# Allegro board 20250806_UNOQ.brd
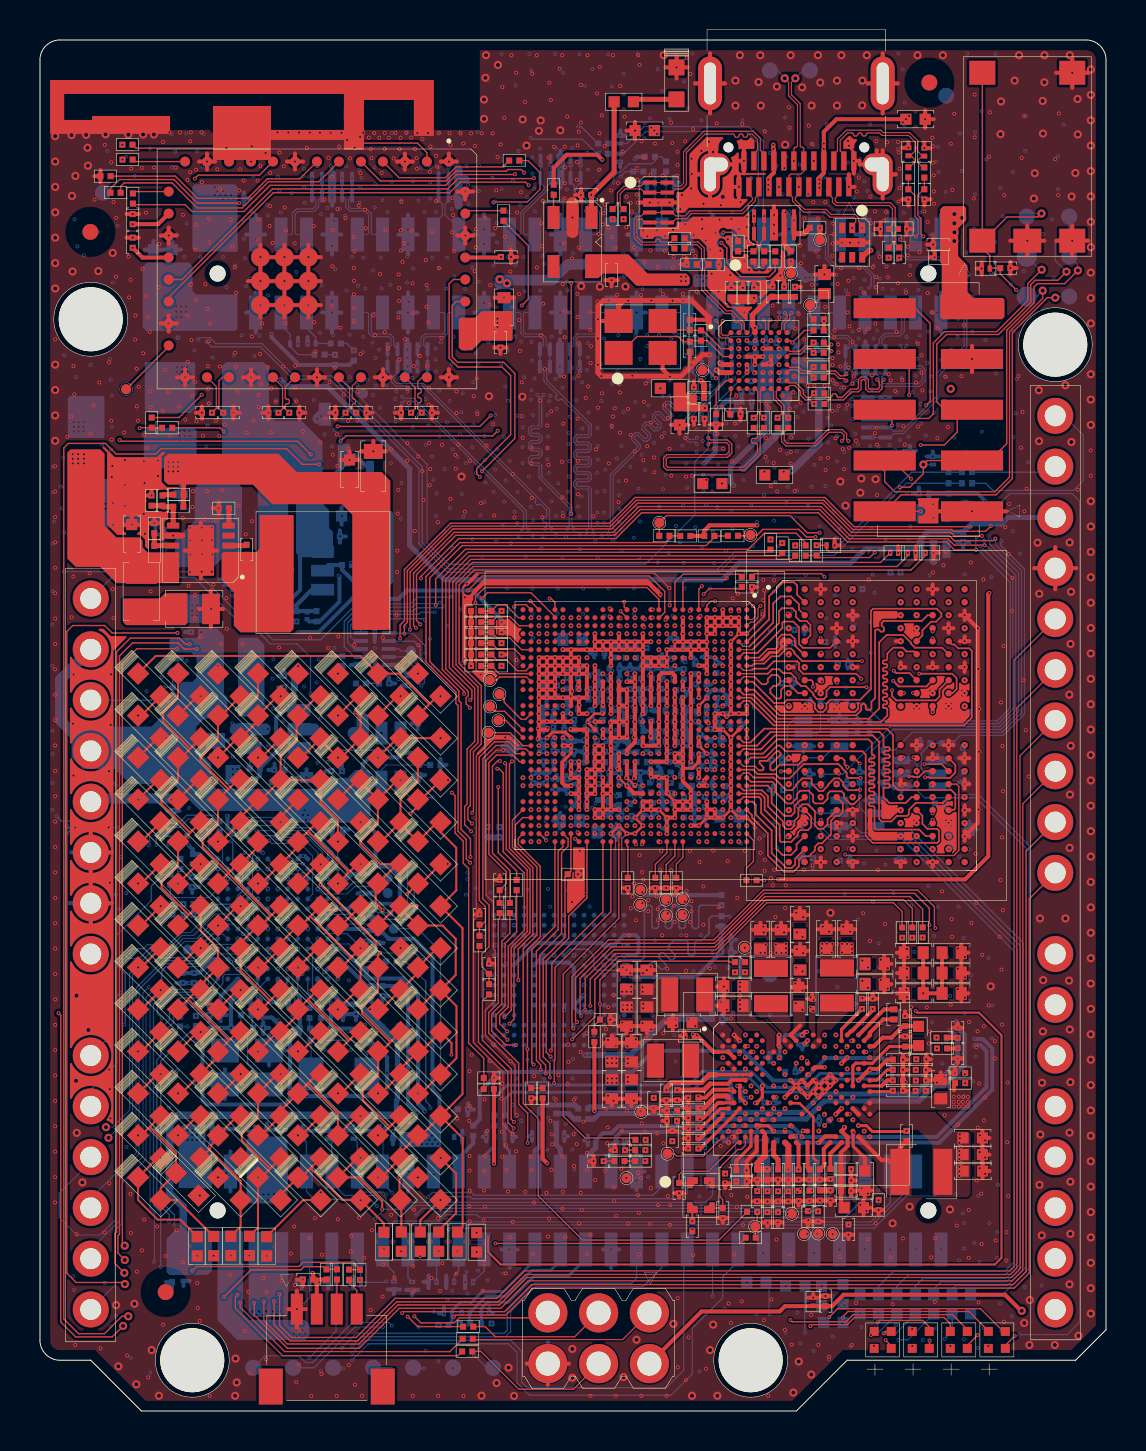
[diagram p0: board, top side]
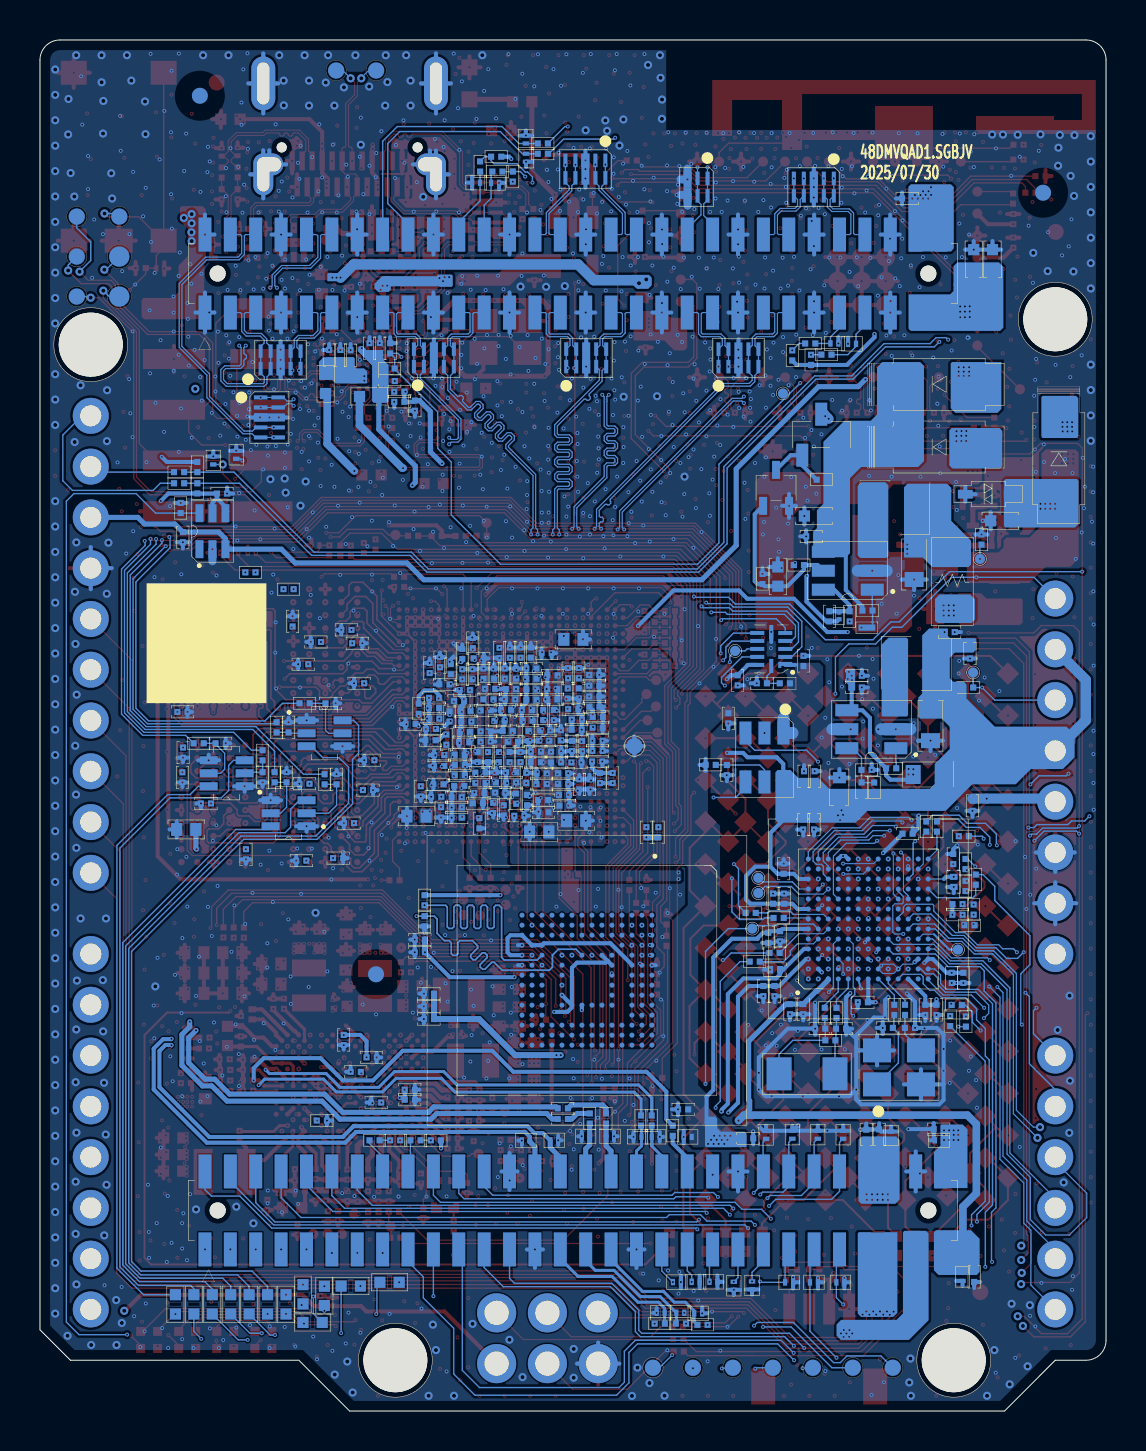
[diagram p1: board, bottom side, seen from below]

Outline 53.34 x 68.58 mm; copper layers: TOP, G2, S3, V4, V5, S6, G7, BOTTOM. Coordinates in mm from the lower left corner of the outline.
Outline path: 0,67.58 0,3.54 arc(0.29,2.83) 1,2.54 2.54,2.54 5.08,0 37.85,0 40.39,2.54 51.82,2.54 53.34,4.06 53.34,67.58 arc(53.05,68.29) 52.34,68.58 1,68.58 arc(0.29,68.29) 0,67.58

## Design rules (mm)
constraint set DEFAULT: min track width 0.066
net group DP_MUX_SSRXN1_C: nets MUX_SSRXN1_C MUX_SSRXP1_C
net group DP_MUX_SSRXN2_C: nets MUX_SSRXN2_C MUX_SSRXP2_C
net group EAR_M_R: nets EAR_M_R EAR_P_R
net group EBI0_CKE: nets EBI0_CKE_0 EBI0_CKE_1
net group EBI0_CLK: nets EBI0_CLK_M EBI0_CLK_P
net group EBI0_DQS_0: nets EBI0_DQS_0_M EBI0_DQS_0_P
net group EBI0_DQS_1: nets EBI0_DQS_1_M EBI0_DQS_1_P
net group EBI1_CKE: nets EBI1_CKE_0 EBI1_CKE_1
net group EBI1_CLK: nets EBI1_CLK_M EBI1_CLK_P
net group EBI1_DQS_0: nets EBI1_DQS_0_M EBI1_DQS_0_P
net group EBI1_DQS_1: nets EBI1_DQS_1_M EBI1_DQS_1_P
net group LINEOUT: nets LINEOUT_M LINEOUT_P
net group LINEOUT_CONN: nets LINEOUT_M_CONN LINEOUT_P_CONN
net group LINEOUT_P_C: nets LINEOUT_M_C LINEOUT_P_C
net group MG_CMD: nets WL_CMD_CLK WL_CMD_DATA
net group MIPI_DSI0_CLK_M: nets MIPI_DSI0_CLK_M MIPI_DSI0_CLK_M_CONN
net group MIPI_DSI0_CLK_P: nets MIPI_DSI0_CLK_P MIPI_DSI0_CLK_P_CONN
net group MIPI_DSI0_L0_M: nets MIPI_DSI0_L0_M MIPI_DSI0_L0_M_CONN
net group MIPI_DSI0_L0_P: nets MIPI_DSI0_L0_P MIPI_DSI0_L0_P_CONN
net group MIPI_DSI0_L1_M: nets MIPI_DSI0_L1_M MIPI_DSI0_L1_M_CONN
net group MIPI_DSI0_L1_P: nets MIPI_DSI0_L1_P MIPI_DSI0_L1_P_CONN
net group MIPI_DSI0_L3_M: nets MIPI_DSI0_L3_M MIPI_DSI0_L3_M_CONN
net group MIPI_DSI0_L3_P: nets MIPI_DSI0_L3_P MIPI_DSI0_L3_P_CONN
net group MUX_SBU1: nets MUX_SBU1 SBU1_AUXP
net group MUX_SBU2: nets MUX_SBU2 SBU2_AUXN
net group MUX_SSRXN2: nets MUX_SSRXN2 MUX_SSRXP2
net group MUX_SSRXP1: nets MUX_SSRXN1 MUX_SSRXP1
net group MUX_SSTXN1_C: nets MUX_SSTXN1 MUX_SSTXP1
net group MUX_SSTXN2: nets MUX_SSTXN2 MUX_SSTXP2
net group MUX_SSTXN2_C: nets MUX_SSTXN2_C MUX_SSTXP2_C
net group MUX_SSTXP1_C: nets MUX_SSTXN1_C MUX_SSTXP1_C
net group SDC1_CLK: nets SDC1_CLK SDC1_CLK_TR
net group VFB_S3: nets VFB_NEG_S3 VFB_S3
net group VFB_S4: nets VFB_NEG_S4 VFB_S4
net group VSNS_S1A_APC: nets VSNS_S1A_APC_M VSNS_S1A_APC_P
net group VSNS_S2A_CX: nets VSNS_S2A_CX_M VSNS_S2A_CX_P
net group CLS_CRITICAL: nets SOC_I2S_D0_R SOC_I2S_SCK SOC_I2S_SCK_R SOC_I2S_WS SOC_I2S_WS_R SOC_UART_RX_SE4 SOC_UART_TX_SE4
net group CLS_LED_MATRIX: nets LED_MATRIX_0 LED_MATRIX_0_R LED_MATRIX_1 LED_MATRIX_1_R LED_MATRIX_2 LED_MATRIX_2_R LED_MATRIX_3 LED_MATRIX_3_R LED_MATRIX_4 LED_MATRIX_4_R LED_MATRIX_5 LED_MATRIX_5_R LED_MATRIX_6 LED_MATRIX_6_R LED_MATRIX_7 LED_MATRIX_7_R LED_MATRIX_8 LED_MATRIX_8_R LED_MATRIX_9 LED_MATRIX_9_R LED_MATRIX_10 LED_MATRIX_10_R LED_MATRIX_11
net group CLS_POWER: nets AVDD1P0V AVDD1P8V AVDD3P0V DVDD1P0V DVDD1P8V VBUS_DIV8 VCOIN VCONN_IN VREF_LPDDR3 VREF_MSM_1P25V VREF_TXDAC_1P25V VREG_L3A_0P6V VREG_L4A_2P96V VREG_L5A_1P232V VREG_L6A_0P9V VREG_L7A_0P664V VREG_L8A_1P0V VREG_L9A_1P0V VREG_L10A_1P3V VREG_L11A_1P0V VREG_L12A_0P9V VREG_L13A_1P8V VREG_L14A_1P8V VREG_L16A_1P8V VREG_L17A_3P0V VREG_L18A_1P8V VREG_L19A_1P8V VREG_L21A_2P96V VREG_L22A_3P3V VREG_S1A_0P8V VREG_XO VSW_S1 VSW_S2 VSW_S3 VSW_S4
net group CLS_SINGEL-50R: nets ANT_CH0 FM_ANT LNBBCLK1 LNBBCLK2 LNBBCLK2_R MUX_XTAL_IN MUX_XTAL_OUT RFCLK2 RTC_SLEEP_CLK RTC_SLEEP_CLK_R SLEEP_CLK SM_LNBBCLK1 SWR_RX_CLK SWR_RX_CLK_R SWR_RX_DATA0 SWR_RX_DATA0_R SWR_RX_DATA1 SWR_RX_DATA1_R SWR_TX_CLK SWR_TX_CLK_R SWR_TX_DATA0 SWR_TX_DATA0_R WCN_RFCLK2 WCN_RFCLK2_R WLAN_XO_CLK
net group EBI0_CA_CS: nets EBI0_CA_0 EBI0_CA_1 EBI0_CA_2 EBI0_CA_3 EBI0_CA_4 EBI0_CA_5 EBI0_CS_0 EBI0_CS_1
net group EBI0_DQ0-7: nets EBI0_DMI_0 EBI0_DQ0 EBI0_DQ1 EBI0_DQ2 EBI0_DQ3 EBI0_DQ4 EBI0_DQ5 EBI0_DQ6 EBI0_DQ7
net group EBI0_DQ8_15: nets EBI0_DMI_1 EBI0_DQ8 EBI0_DQ9 EBI0_DQ10 EBI0_DQ11 EBI0_DQ12 EBI0_DQ13 EBI0_DQ14 EBI0_DQ15
net group EBI1_CA_CS: nets EBI1_CA_0 EBI1_CA_1 EBI1_CA_2 EBI1_CA_3 EBI1_CA_4 EBI1_CA_5 EBI1_CS_0 EBI1_CS_1
net group EBI1_DQ0_7: nets EBI1_DMI_0 EBI1_DQ0 EBI1_DQ1 EBI1_DQ2 EBI1_DQ3 EBI1_DQ4 EBI1_DQ5 EBI1_DQ6 EBI1_DQ7
net group EBI1_DQ8_15: nets EBI1_DMI_1 EBI1_DQ8 EBI1_DQ9 EBI1_DQ10 EBI1_DQ11 EBI1_DQ12 EBI1_DQ13 EBI1_DQ14 EBI1_DQ15
net group MIPI_DSI0_L2_M: nets MIPI_DSI0_L2_M
net group MIPI_DSI0_L2_P: nets MIPI_DSI0_L2_P
net group SDC1: nets SDC1_CMD SDC1_DATA_0 SDC1_DATA_1 SDC1_DATA_2 SDC1_DATA_3 SDC1_DATA_4 SDC1_DATA_5 SDC1_DATA_6 SDC1_DATA_7 SDC1_RCLK

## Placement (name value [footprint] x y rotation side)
ANT1  CLIP2P  [ANT2_1920X400]  15.71 64.83 0 top
C501  2.2UF/6.3V  [C0201_H04_T30]  42.72 19.84 0 top
C502  1UF/6.3V  [C0201_H040]  43.29 19.51 180 top
C503  1UF/6.3V  [C0201_H040]  43.29 18.49 180 top
C504  1UF/6.3V  [C0201_H040]  41.13 20.37 180 top
C505  1UF/6.3V  [C0201_H040]  42.93 17.58 90 top
C506  1UF/6.3V  [C0201_H040]  41.66 20.37 180 top
C507  680PF/25V  [C0201_H030]  42.93 17.07 90 top
C508  470PF/50V  [C0201_H030]  42.93 16.54 90 top
C509  680PF/25V  [C0201_H030]  42.93 16.02 90 top
C510  33PF/50V  [C0201_H030]  44.08 17.06 90 top
C511  33PF/50V  [C0201_H030]  44.08 16.53 90 top
C512  100NF/6.3V  [C0201_H030]  44.1 17.59 90 top
C513  100NF/6.3V  [C0201_H030]  27.18 14.61 270 bottom
C514  100NF/6.3V  [C0201_H030]  27.18 15.14 270 bottom
C601  4.7UF/10V  [C0402_H060]  40.72 10.17 90 top
C602  1UF/10V  [C0201_H030]  40.34 11.53 90 top
C603  100NF/10V  [C0201_H030]  40.34 11.01 90 top
C604  10UF/10V  [C0402_H060]  46.68 12 90 top
C605  10UF/10V  [C0402_H060]  46.67 12.83 90 top
C606  10UF/10V  [C0402_H060]  46.67 13.66 90 top
C607  10UF/6.3V  [C0402_H07_T30]  45.07 16.1 180 top
C608  4.7UF/10V  [C0402_H060]  41.27 11.52 0 top
C609  27NF/16V  [C0201_H030]  43.36 13.76 0 top
C610  4.7UF/6.3V  [C0201_H060]  40.46 9.07 0 top
C701  7PF/25V  [C0201_H030]  31.98 11.15 0 top
C702  7PF/25V  [C0201_H030]  34.16 9.91 0 top
C703  1000PF/50V  [C0201_H030]  32.64 9.25 180 top
C704  1UF/6.3V  [C0201_H040]  34.28 11.63 0 top
C705  1UF/6.3V  [C0201_H040]  35.1 11.48 90 top
C706  4.7UF/6.3V  [C0201_H060]  35.1 12.04 90 top
C707  10PF/50V  [C0201_H030]  29.02 13.05 270 top
C708  10UF/6.3V  [C0402_H07_T30]  43.71 22.92 270 top
C709  10UF/6.3V  [C0402_H07_T30]  45.62 22.92 90 top
C710  10UF/6.3V  [C0402_H07_T30]  45.62 21.91 90 top
C711  10UF/6.3V  [C0402_H07_T30]  43.71 21.91 270 top
C712  10UF/6.3V  [C0402_H07_T30]  45.62 20.89 90 top
C713  10UF/6.3V  [C0402_H07_T30]  43.71 20.89 270 top
C714  1UF/6.3V  [C0201_H040]  31.62 15.02 270 top
C715  1UF/6.3V  [C0201_H040]  31.62 14.51 270 top
C716  100NF/10V  [C0201_H030]  31.64 13.75 180 top
C717  100NF/10V  [C0201_H030]  36.4 9.69 0 top
C718  100NF/6.3V  [C0201_H030]  38.5 10.77 0 top
C719  100NF/6.3V  [C0201_H030]  30.71 15.41 0 top
C720  0  [C0201_H030]  28.99 12.5 270 top
C721  22PF/50V  [C0201_H030]  27.95 12.5 270 top
C801  1UF/6.3V  [C0201_H040]  38.14 18.56 180 bottom
C802  1UF/6.3V  [C0201_H040]  36.75 17.69 90 bottom
C803  1UF/6.3V  [C0201_H040]  34.84 15.57 90 bottom
C804  1UF/6.3V  [C0201_H040]  34.84 16.07 90 bottom
C805  1UF/6.3V  [C0201_H040]  35.89 10.74 0 top
C806  10UF/6.3V  [C0402_H07_T30]  34.7 20.28 270 top
C807  10UF/6.3V  [C0402_H07_T30]  34.7 21.23 270 top
C808  10UF/6.3V  [C0402_H07_T30]  41.76 21.35 90 top
C809  10UF/6.3V  [C0402_H07_T30]  41.76 22.36 90 top
C810  10UF/6.3V  [C0402_H07_T30]  38.02 24.33 180 top
C811  10UF/6.3V  [C0402_H07_T30]  38.03 22.54 180 top
C812  1UF/6.3V  [C0201_H040]  37.96 11.83 0 top
C813  1UF/6.3V  [C0201_H040]  32.69 14.15 270 top
C814  1UF/6.3V  [C0201_H040]  32.69 13.64 270 top
C815  2.2UF/6.3V  [C0201_H030]  32.69 14.66 270 top
C816  2.2UF/6.3V  [C0201_H030]  31.88 15.8 0 top
C817  1UF/6.3V  [C0201_H040]  32.69 15.67 270 top
C818  4.7UF/6.3V  [C0201_H060]  31.34 15.8 0 top
C819  2.2UF/6.3V  [C0201_H030]  32.69 15.16 270 top
C820  2.2UF/6.3V  [C0201_H030]  32.69 13.13 270 top
C821  2.2UF/6.3V  [C0201_H030]  37.45 10.74 0 top
C822  4.7UF/6.3V  [C0201_H060]  37.45 11.83 0 top
C823  4.7UF/6.3V  [C0201_H060]  36.4 11.83 0 top
C824  1UF/6.3V  [C0201_H040]  35.89 11.83 0 top
C825  2.2UF/6.3V  [C0201_H030]  36.93 11.83 0 top
C826  4.7UF/6.3V  [C0201_H060]  38.51 11.83 0 top
C827  1UF/6.3V  [C0201_H040]  39.55 11.85 0 top
C828  1UF/6.3V  [C0201_H040]  39.02 11.83 0 top
C829  4.7UF/6.3V  [C0201_H060]  37.96 10.76 0 top
C830  4.7UF/6.3V  [C0201_H060]  36.93 10.74 0 top
C831  4.7UF/6.3V  [C0201_H060]  39.03 10.79 0 top
C832  1UF/6.3V  [C0201_H040]  39.55 10.79 0 top
C901  1UF/10V  [C0201_H030]  36.52 15.43 270 bottom
C902  1UF/10V  [C0201_H030]  37.54 16.97 270 bottom
C1001  1UF/10V  [C0201_H030]  38.63 20.37 180 top
C1002  10UF/10V  [C0402_H060]  37.97 20.73 180 top
C1003  10UF/10V  [C0402_H060]  32.15 19.43 270 top
C1004  1UF/10V  [C0201_H030]  32.5 18.76 270 top
C1005  10UF/6.3V  [C0402_H07_T30]  29.35 19.73 0 top
C1006  10UF/6.3V  [C0402_H07_T30]  29.35 21.57 180 top
C1007  10UF/6.3V  [C0402_H07_T30]  30.37 21.57 180 top
C1008  10UF/6.3V  [C0402_H07_T30]  30.37 19.73 0 top
C1009  10UF/6.3V  [C0402_H07_T30]  29.6 17.94 180 top
C1010  10UF/6.3V  [C0402_H07_T30]  28.61 16.1 0 top
C1011  10UF/6.3V  [C0402_H07_T30]  28.61 17.94 180 top
C1012  10UF/6.3V  [C0402_H07_T30]  29.6 16.1 0 top
C1101  100NF/6.3V  [C0201_H030]  15.14 37.52 0 bottom
C1102  100NF/6.3V  [C0201_H030]  18.43 36.55 180 bottom
C1103  100NF/6.3V  [C0201_H030]  18.9 34.65 180 bottom
C1104  100NF/6.3V  [C0201_H030]  14.58 31.75 0 bottom
C1105  4.7UF/6.3V  [C0201_H060]  17.22 36.4 270 bottom
C1106  4.7UF/6.3V  [C0201_H060]  18.97 32.06 180 bottom
C1201  100NF/6.3V  [C0201_H030]  23 26.31 180 top
C1202  33PF/50V  [C0201_H030]  21.99 24.59 180 top
C1203  33PF/50V  [C0201_H030]  22.47 22.12 180 top
C1601  2.7PF/50V  [C0201_H030]  19.35 49.94 90 top
C1602  2.7PF/50V  [C0201_H030]  18.31 49.94 270 top
C1603  2.7PF/50V  [C0201_H030]  9.42 49.94 90 top
C1604  2.7PF/50V  [C0201_H030]  8.36 49.94 270 top
C1701  1UF/6.3V  [C0201_H040]  30.38 32.71 180 bottom
C1702  100NF/6.3V  [C0201_H030]  24.68 31.66 180 bottom
C1703  100NF/6.3V  [C0201_H030]  25.32 31.66 180 bottom
C1704  100NF/6.3V  [C0201_H030]  26.66 35.11 90 bottom
C1705  10UF/6.3V  [C0402_H07_T30]  26.51 29.53 90 bottom
C1706  10UF/6.3V  [C0402_H07_T30]  39.34 23.62 180 top
C1707  10UF/6.3V  [C0402_H07_T30]  28.36 28.97 270 bottom
C1708  10UF/6.3V  [C0402_H07_T30]  40.37 23.62 180 top
C1709  100NF/6.3V  [C0201_H030]  27.51 32.44 90 bottom
C1710  100NF/6.3V  [C0201_H030]  28.53 32.45 270 bottom
C1711  2.2UF/6.3V  [C0201_H030]  29.77 31.95 270 bottom
C1712  2.2UF/6.3V  [C0201_H030]  29.85 32.71 0 bottom
C1713  100NF/6.3V  [C0201_H030]  28.24 31.9 270 bottom
C1714  470NF/6.3V  [C0201_H030]  27.12 30.82 90 bottom
C1715  470NF/6.3V  [C0201_H030]  28.24 31.36 270 bottom
C1716  470NF/6.3V  [C0201_H030]  29.29 32.71 0 bottom
C1717  100NF/6.3V  [C0201_H030]  27.51 32.98 90 bottom
C1718  100NF/6.3V  [C0201_H030]  28.97 30.56 180 bottom
C1719  100NF/6.3V  [C0201_H030]  28.53 32.98 270 bottom
C1720  100NF/6.3V  [C0201_H030]  27.16 31.36 90 bottom
C1721  100NF/6.3V  [C0201_H030]  27.09 30.28 90 bottom
C1722  2.2UF/6.3V  [C0201_H030]  28.11 33.53 270 bottom
C1723  2.2UF/6.3V  [C0201_H030]  28.15 29.95 270 bottom
C1724  100NF/6.3V  [C0201_H030]  27.16 31.9 90 bottom
C1725  100NF/6.3V  [C0201_H030]  28.16 30.56 270 bottom
C1727  4.7UF/6.3V  [C0201_H060]  32.33 31.8 90 bottom
C1728  2.2UF/6.3V  [C0201_H030]  28.78 37.94 0 bottom
C1729  100NF/6.3V  [C0201_H030]  31.04 35.04 90 bottom
C1730  100NF/6.3V  [C0201_H030]  31.04 34 90 bottom
C1731  100NF/6.3V  [C0201_H030]  32.34 32.82 90 bottom
C1732  470NF/6.3V  [C0201_H030]  28.75 36.09 270 bottom
C1733  10NF/10V  [C0201_H030]  32.37 35.52 90 bottom
C1734  1UF/6.3V  [C0201_H040]  28.75 35.58 270 bottom
C1735  1UF/6.3V  [C0201_H040]  28.94 34.54 270 bottom
C1736  2.2UF/6.3V  [C0201_H030]  31.04 33.49 90 bottom
C1737  2.2UF/6.3V  [C0201_H030]  31.14 36.89 0 bottom
C1738  470NF/6.3V  [C0201_H030]  32.85 34.74 180 bottom
C1739  100NF/6.3V  [C0201_H030]  30.81 36.12 90 bottom
C1740  100NF/6.3V  [C0201_H030]  28.75 37.14 270 bottom
C1741  100NF/6.3V  [C0201_H030]  28.75 36.63 270 bottom
C1742  1UF/6.3V  [C0201_H040]  31.44 32.72 180 bottom
C1743  1UF/6.3V  [C0201_H040]  26.5 32.44 90 bottom
C1801  10UF/6.3V  [C0402_H07_T30]  34.5 29.76 270 bottom
C1802  10UF/6.3V  [C0402_H07_T30]  26.65 38.6 90 bottom
C1803  10UF/6.3V  [C0402_H07_T30]  36.04 23.59 180 top
C1804  10UF/6.3V  [C0402_H07_T30]  37.08 23.59 180 top
C1805  1UF/6.3V  [C0201_H040]  27.7 36.8 270 bottom
C1806  1UF/6.3V  [C0201_H040]  27.7 36.12 270 bottom
C1807  2.2UF/6.3V  [C0201_H030]  27.63 34.81 180 bottom
C1808  100NF/6.3V  [C0201_H030]  29.81 35.6 270 bottom
C1809  100NF/6.3V  [C0201_H030]  29.94 34.01 270 bottom
C1810  100NF/6.3V  [C0201_H030]  32.08 36.06 270 bottom
C1811  100NF/6.3V  [C0201_H030]  32.08 33.96 270 bottom
C1812  100NF/6.3V  [C0201_H030]  30.9 35.6 270 bottom
C1813  100NF/6.3V  [C0201_H030]  27.71 35.6 270 bottom
C1814  1UF/6.3V  [C0201_H040]  30.02 35.08 270 bottom
C1815  1UF/6.3V  [C0201_H040]  32.12 33.46 270 bottom
C1816  1UF/6.3V  [C0201_H040]  30.34 34.53 90 bottom
C1817  1UF/6.3V  [C0201_H040]  31.3 31.93 90 bottom
C1818  4.7UF/6.3V  [C0201_H060]  30.61 36.89 0 bottom
C1819  470NF/6.3V  [C0201_H030]  29.78 36.11 270 bottom
C1820  2.2UF/6.3V  [C0201_H030]  29.52 36.88 0 bottom
C1821  100NF/6.3V  [C0201_H030]  32.05 35.01 270 bottom
C1822  1UF/6.3V  [C0201_H040]  30.08 36.89 0 bottom
C1823  1UF/6.3V  [C0201_H040]  29.68 33.48 90 bottom
C1824  4.7UF/6.3V  [C0201_H060]  28.06 34.04 90 bottom
C1825  100NF/6.3V  [C0201_H030]  28.89 33.77 180 bottom
C1826  2.2UF/6.3V  [C0201_H030]  26.21 33.27 180 bottom
C1827  100NF/6.3V  [C0201_H030]  26.72 33.27 180 bottom
C1828  100NF/6.3V  [C0201_H030]  27.27 33.8 0 bottom
C1829  1UF/6.3V  [C0201_H040]  25.44 33.53 270 bottom
C1830  1UF/6.3V  [C0201_H040]  34.29 31 180 bottom
C1831  1UF/6.3V  [C0201_H040]  33.84 37.17 0 bottom
C1833  1UF/6.3V  [C0201_H040]  27.99 37.91 270 bottom
C1834  1UF/6.3V  [C0201_H040]  26.35 31.34 0 bottom
C1835  1UF/6.3V  [C0201_H040]  30.92 32.71 180 bottom
C1836  100NF/6.3V  [C0201_H030]  33.51 30.73 270 bottom
C1837  1UF/6.3V  [C0201_H040]  30.35 37.92 180 bottom
C1838  1UF/6.3V  [C0201_H040]  29.35 29.77 90 bottom
C1839  1UF/6.3V  [C0201_H040]  33.36 32.27 270 bottom
C1840  1UF/6.3V  [C0201_H040]  25.44 33.02 270 bottom
C1841  1UF/6.3V  [C0201_H040]  25.84 31.34 0 bottom
C1842  1UF/6.3V  [C0201_H040]  33.27 29.95 180 bottom
C1843  100NF/6.3V  [C0201_H030]  25.46 32.49 90 bottom
C1844  100NF/6.3V  [C0201_H030]  29.51 30.63 0 bottom
C1845  4.7UF/6.3V  [C0201_H060]  32.21 37.87 0 bottom
C1846  4.7UF/6.3V  [C0201_H060]  31.7 36.85 0 bottom
C1847  470NF/6.3V  [C0201_H030]  32.21 36.85 0 bottom
C1848  470NF/6.3V  [C0201_H030]  32.78 37.11 0 bottom
C1849  4.7UF/6.3V  [C0201_H060]  28.98 35.06 270 bottom
C1850  470NF/6.3V  [C0201_H030]  33.36 32.81 270 bottom
C1851  1UF/6.3V  [C0201_H040]  25.44 34.18 90 bottom
C1901  1UF/6.3V  [C0201_H040]  29.01 31.66 0 bottom
C1902  1UF/6.3V  [C0201_H040]  33.1 36.35 270 bottom
C1903  1UF/6.3V  [C0201_H040]  32.33 32.31 90 bottom
C1904  1UF/6.3V  [C0201_H040]  30.14 30.05 180 bottom
C1905  1UF/6.3V  [C0201_H040]  29.83 37.93 0 bottom
C1906  100NF/6.3V  [C0201_H030]  29.29 37.93 0 bottom
C1907  100NF/6.3V  [C0201_H030]  30.31 30.93 90 bottom
C1908  1UF/6.3V  [C0201_H040]  30.53 31.7 0 bottom
C1909  1UF/6.3V  [C0201_H040]  30.66 30.17 180 bottom
C1910  1UF/6.3V  [C0201_H040]  29.77 31.44 270 bottom
C1911  100NF/6.3V  [C0201_H030]  26.48 34.59 90 bottom
C1912  470NF/6.3V  [C0201_H030]  28.16 34.82 180 bottom
C1913  1UF/6.3V  [C0201_H040]  31.39 37.65 90 bottom
C1914  1UF/6.3V  [C0201_H040]  32.01 34.48 270 bottom
C1915  1UF/6.3V  [C0201_H040]  33.61 34.63 270 bottom
C1916  1UF/6.3V  [C0201_H040]  33.62 35.16 270 bottom
C1917  1UF/6.3V  [C0201_H040]  26.49 34.08 90 bottom
C1918  100NF/6.3V  [C0201_H030]  25.43 34.72 90 bottom
C1919  100NF/6.3V  [C0201_H030]  25.61 35.74 90 bottom
C1920  100NF/6.3V  [C0201_H030]  25.61 36.28 90 bottom
C1921  1UF/6.3V  [C0201_H040]  25.61 36.82 90 bottom
C1922  100NF/6.3V  [C0201_H030]  26.92 36.91 0 bottom
C1923  100NF/6.3V  [C0201_H030]  26.38 36.91 0 bottom
C1924  1UF/6.3V  [C0201_H040]  26.93 35.89 180 bottom
C1925  470NF/6.3V  [C0201_H030]  33.4 31.35 270 bottom
C1926  100NF/6.3V  [C0201_H030]  32.49 30.7 270 bottom
C1927  100NF/6.3V  [C0201_H030]  32.36 31.27 270 bottom
C1928  100NF/6.3V  [C0201_H030]  32.49 30.19 270 bottom
C1929  1UF/6.3V  [C0201_H040]  32.49 29.68 270 bottom
C1930  1UF/6.3V  [C0201_H040]  31.43 30.4 90 bottom
C1931  1UF/6.3V  [C0201_H040]  31.35 29.4 180 bottom
C1932  1UF/6.3V  [C0201_H040]  31.35 30.92 90 bottom
C1933  1UF/6.3V  [C0201_H040]  31.3 31.42 90 bottom
C1934  1UF/6.3V  [C0201_H040]  33.78 34.11 270 bottom
C1935  1UF/6.3V  [C0201_H040]  31.68 38.41 0 bottom
C1936  2.2UF/6.3V  [C0201_H030]  33.62 35.67 270 bottom
C1937  1UF/6.3V  [C0201_H040]  33.32 37.46 0 bottom
C1938  2.2UF/6.3V  [C0201_H030]  33.01 33.58 180 bottom
C1939  100NF/6.3V  [C0201_H030]  25.6 35.23 90 bottom
C1940  100NF/6.3V  [C0201_H030]  26.38 35.89 180 bottom
C2101  1UF/6.3V  [C0201_H040]  22.4 28.95 0 bottom
C2102  100NF/10V  [C0201_H030]  23 28.95 0 bottom
C2103  2.2UF/6.3V  [C0201_H030]  33.88 20.24 270 bottom
C2104  100NF/6.3V  [C0201_H030]  33.88 20.88 270 bottom
C2105  2.2UF/6.3V  [C0201_H030]  33.88 19.61 270 bottom
C2106  2.2UF/6.3V  [C0201_H030]  34.33 23.58 270 bottom
C2107  1UF/6.3V  [C0201_H040]  34.33 22.95 270 bottom
C2201  1UF/6.3V  [C0201_H040]  38.01 39.07 270 bottom
C2202  1UF/6.3V  [C0201_H040]  40.7 39.5 0 bottom
C2203  1UF/6.3V  [C0201_H040]  33.8 33.55 270 bottom
C2204  100NF/6.3V  [C0201_H030]  38.42 27.66 90 bottom
C2205  1UF/6.3V  [C0201_H040]  43.03 27.85 180 bottom
C2206  1UF/6.3V  [C0201_H040]  37.88 29.41 270 bottom
C2207  100NF/6.3V  [C0201_H030]  45.03 30.39 270 bottom
C2208  1UF/6.3V  [C0201_H040]  39.53 38.47 270 bottom
C2209  1UF/6.3V  [C0201_H040]  37.37 36.4 270 bottom
C2210  1UF/6.3V  [C0201_H040]  34.8 34.36 270 bottom
C2211  1UF/6.3V  [C0201_H040]  46.21 34.97 90 bottom
C2212  1UF/6.3V  [C0201_H040]  46.21 31.7 180 bottom
C2213  1UF/6.3V  [C0201_H040]  40.27 27.53 270 bottom
C2214  1UF/6.3V  [C0201_H040]  46.18 32.94 180 bottom
C2215  10UF/6.3V  [C0402_H07_T30]  46.02 29.09 270 bottom
C2216  4.7UF/6.3V  [C0201_H060]  36.86 32.55 270 bottom
C2217  100NF/6.3V  [C0201_H030]  40.11 31.38 270 bottom
C2218  1UF/6.3V  [C0201_H040]  37.47 38.41 90 bottom
C2219  1UF/6.3V  [C0201_H040]  40.17 37.36 270 bottom
C2220  1UF/6.3V  [C0201_H040]  36.93 31.06 90 bottom
C2501  2.2UF/6.3V  [C0201_H04_T30]  16.56 22.07 270 bottom
C2502  10UF/6.3V  [C0402_H07_T30]  13.34 31.2 0 bottom
C2503  100NF/6.3V  [C0201_H030]  16.59 21.01 180 bottom
C2504  100NF/6.3V  [C0201_H030]  16.1 25.63 0 bottom
C2505  100NF/6.3V  [C0201_H030]  17.14 21.01 180 bottom
C2506  100NF/6.3V  [C0201_H030]  12.17 20.45 270 bottom
C2507  100NF/6.3V  [C0201_H030]  7.43 24.82 90 bottom
C2508  100NF/6.3V  [C0201_H030]  7.43 25.36 90 bottom
C2509  100NF/6.3V  [C0201_H030]  16.13 27.13 0 bottom
C2510  100NF/6.3V  [C0201_H030]  15.11 31.75 0 bottom
C2511  100NF/6.3V  [C0201_H030]  14.61 29.34 180 bottom
C2512  100NF/6.3V  [C0201_H030]  7.65 27.61 0 bottom
C2513  100NF/6.3V  [C0201_H030]  16.66 25.63 0 bottom
C2514  4.7UF/6.3V  [C0201_H060]  9.93 28.88 90 bottom
C2515  100NF/6.3V  [C0201_H030]  16.9 23.67 180 bottom
C2516  100NF/6.3V  [C0201_H030]  16.31 23.75 180 bottom
C2517  1UF/6.3V  [C0201_H040]  7.72 21.67 180 bottom
C2518  100NF/6.3V  [C0201_H030]  7.14 21.67 180 bottom
C2519  100NF/6.3V  [C0201_H030]  15.15 29.34 180 bottom
C2520  1UF/6.3V  [C0201_H040]  9.04 20.07 180 bottom
C2521  100NF/6.3V  [C0201_H030]  8.48 20.07 180 bottom
C2522  12PF/50V  [C0201_H030]  10.92 19.16 270 bottom
C2523  12PF/50V  [C0201_H030]  9.81 19.16 90 bottom
C2524  4.7UF/6.3V  [C0201_H060]  15.82 20.1 180 bottom
C2525  2.2UF/6.3V  [C0201_H04_T30]  7.62 26.47 180 bottom
C2526  100NF/6.3V  [C0201_H030]  15.15 20.1 180 bottom
C2527  7PF/25V  [C0201_H030]  13.26 19.13 90 bottom
C2528  7PF/25V  [C0201_H030]  14.3 19.13 270 bottom
C2529  100NF/6.3V  [C0201_H030]  44.23 45.89 90 bottom
C2601  220NF/10V  [C0201_H030]  42.99 57.94 0 top
C2602  220NF/10V  [C0201_H030]  42.46 57.94 0 top
C2603  220NF/10V  [C0201_H030]  28.65 59.87 0 top
C2604  220NF/10V  [C0201_H030]  29.2 59.87 0 top
C2605  100NF/6.3V  [C0201_H030]  48.3 57.17 90 top
C2607  10UF/10V  [C0402_H060]  43.81 64.62 90 top
C2608  10UF/10V  [C0402_H060]  30.26 64.05 270 top
C2609  100NF/6.3V  [C0201_H030]  44.94 58.35 270 top
C2610  100NF/6.3V  [C0201_H030]  13.41 6.58 270 top
C2611  100NF/10V  [C0201_H030]  39.3 5.5 180 top
C2614  100NF/6.3V  [C0201_H030]  46.19 43.71 180 bottom
C2615  100NF/6.3V  [C0201_H030]  7.82 38.96 90 bottom
C2616  100NF/6.3V  [C0201_H030]  6.81 37.9 180 bottom
C2617  100NF/10V  [C0201_H030]  6.68 30.28 180 bottom
C2618  0.1UF/50V  [C0402_H060]  5.68 57.61 0 bottom
C2619  0.1UF/50V  [C0402_H060]  6.62 57.61 0 bottom
C2620  100NF/6.3V  [C0201_H030]  9.95 60.65 270 bottom
C2621  100NF/10V  [C0201_H030]  11.35 13.83 0 bottom
C2622  100NF/10V  [C0201_H030]  12 13.82 0 bottom
C2623  100NF/6.3V  [C0201_H030]  21.16 15.09 270 bottom
C2624  100NF/6.3V  [C0201_H030]  17.91 13.64 90 bottom
C2625  100NF/6.3V  [C0201_H030]  6.6 6.71 180 bottom
C2626  100NF/6.3V  [C0201_H030]  8.37 14.1 270 bottom
C2627  330NF/6.3V  [C0201_H030]  32 58.66 270 top
C2628  330NF/6.3V  [C0201_H030]  32 58.15 270 top
C2629  330NF/6.3V  [C0201_H030]  44.25 61.95 0 top
C2630  330NF/6.3V  [C0201_H030]  43.45 61.96 0 top
C2631  0.1UF/50V  [C0402_H060]  5.29 44.53 270 bottom
C2632  220PF/25V  [C0201_H030]  45.92 17.89 0 top
C2633  220PF/25V  [C0201_H030]  45.92 18.92 180 top
C2701  100NF/10V  [C0201_H030]  42.2 31.7 180 bottom
C2702  100NF/10V  [C0201_H030]  44.3 33.4 90 bottom
C2703  100NF/10V  [C0201_H030]  40.9 34.2 0 bottom
C2704  100NF/10V  [C0201_H030]  38.8 35.4 90 bottom
C2705  100NF/10V  [C0201_H030]  38.5 31.6 0 bottom
C2706  100NF/10V  [C0201_H030]  41 31.7 0 bottom
C2801  4.7UF/10V  [C0402_H060]  14.61 44.77 270 bottom
C2802  100NF/10V  [C0201_H030]  14.75 43.75 270 bottom
C2803  120PF/25V  [C0201_H030]  13.84 39.75 0 bottom
C2804  22UF/6.3V  [C0603_H100]  9.6 42.34 180 bottom
C2805  4.7UF/6.3V  [C0201_H060]  12.47 36.78 90 bottom
C2806  100NF/6.3V  [C0201_H030]  12.47 36.2 90 bottom
C2807  120PF/25V  [C0201_H030]  12.23 31.19 0 bottom
C2808  4.7UF/10V  [C0402_H060]  16.42 41.74 0 bottom
C2809  22UF/6.3V  [C0603_H100]  8.78 34.28 180 bottom
C2810  22UF/25V  [C0805_H150]  5.07 40.99 0 top
C2811  22UF/25V  [C0805_H150]  7.72 40.12 90 top
C2812  0.1UF/50V  [C0402_H060]  4.59 43.86 180 top
C2813  100NF/16V  [C0201_H030]  10.34 43.08 180 top
C2814  22PF/50V  [C0201_H030]  6.13 45.54 0 top
C2815  22UF/10V  [C0603_H090]  16.68 47.25 180 top
C2816  10UF/10V  [C0402_H060]  15.49 47.09 180 top
C2901  4.7UF/6.3V  [C0201_H060]  4.64 59.62 180 top
C2907  4.7UF/6.3V  [C0201_H060]  23.32 57.73 90 top
C2909  4.7UF/6.3V  [C0201_H060]  4.64 58.44 180 top
C2911  10UF/6.3V  [C0402_H07_T30]  23.22 55.21 180 top
C2912  4.7UF/6.3V  [C0201_H060]  23.04 53.45 0 top
C2921  2.7PF/50V  [C0201_H030]  15.04 49.94 270 top
C2922  2.7PF/50V  [C0201_H030]  16.08 49.94 90 top
C2923  2.7PF/50V  [C0201_H030]  12.73 49.94 90 top
C2924  2.7PF/50V  [C0201_H030]  11.68 49.94 270 top
C3001  1UF/6.3V  [C0201_H040]  34.59 55.94 180 top
C3002  100NF/6.3V  [C0201_H030]  35.17 55.93 180 top
C3003  1000PF/50V  [C0201_H030]  35.73 55.94 180 top
C3004  1UF/6.3V  [C0201_H040]  38.31 52.82 0 bottom
C3005  100NF/6.3V  [C0201_H030]  38.87 52.82 0 bottom
C3006  1000PF/50V  [C0201_H030]  37.8 52.81 0 bottom
C3007  1UF/6.3V  [C0201_H040]  34.58 50.29 180 bottom
C3008  100NF/6.3V  [C0201_H030]  35.36 50.48 270 bottom
C3009  1000PF/50V  [C0201_H030]  35.36 50.99 270 bottom
C3010  1UF/6.3V  [C0201_H040]  37.77 55.98 180 top
C3011  100NF/6.3V  [C0201_H030]  37.23 55.98 180 top
C3012  1000PF/50V  [C0201_H030]  36.65 55.99 180 top
C3013  1UF/6.3V  [C0201_H040]  36.34 53.16 0 bottom
C3014  100NF/6.3V  [C0201_H030]  35.84 51.52 90 bottom
C3015  1000PF/50V  [C0201_H030]  36.85 53.16 0 bottom
C3016  10UF/10V  [C0402_H060]  32 49.81 0 top
C3017  100NF/10V  [C0201_H030]  33.25 49.89 0 top
C3018  1000PF/50V  [C0201_H030]  32.72 49.89 0 top
C3019  100NF/10V  [C0201_H030]  35.7 57.76 180 top
C3020  100NF/10V  [C0201_H030]  36.24 57.76 180 top
C3021  36PF/50V  [C0201_H030]  32.51 53.24 0 top
C3022  36PF/50V  [C0201_H030]  32.51 54.33 180 top
C3025  1UF/6.3V  [C0201_H040]  27.33 60.83 270 top
C3026  1UF/6.3V  [C0201_H040]  28.6 56.82 0 top
C3027  10UF/6.3V  [C0402_H07_T30]  39.25 56.37 180 top
C3028  100NF/6.3V  [C0201_H030]  35.82 53.16 0 bottom
D2801  SX34  [SMA_H240]  8.35 51.36 270 bottom
D2802  SX34  [SMA_H240]  2.36 47.63 0 bottom
D2803  SX34  [SMA_H240]  8.35 48.22 270 bottom
D26001  DF2B7ASL  [D_06X03_H030_TOSHIBA]  44.67 47.55 180 bottom
D26002  DF2B7ASL  [D_06X03_H030_TOSHIBA]  43.52 47.83 180 bottom
D26003  DF2B7ASL  [D_06X03_H030_TOSHIBA]  44.97 57.71 90 top
D26005  DF2B7ASL  [D_06X03_H030_TOSHIBA]  44.51 42.93 270 top
D26006  DF2B7ASL  [D_06X03_H030_TOSHIBA]  43.62 42.93 270 top
D26007  DF2B7ASL  [D_06X03_H030_TOSHIBA]  42.74 42.93 270 top
D26008  DF2B7ASL  [D_06X03_H030_TOSHIBA]  39.56 43.3 270 top
D26009  DF2B7ASL  [D_06X03_H030_TOSHIBA]  47.32 57.15 90 top
D26017  DF2B7ASL  [D_06X03_H030_TOSHIBA]  38.69 5.47 0 top
D26046  DF2B7ASL  [D_06X03_H030_TOSHIBA]  29.03 63.6 180 bottom
D26047  DF2B7ASL  [D_06X03_H030_TOSHIBA]  29.02 62.69 0 bottom
D26048  DF2B7ASL  [D_06X03_H030_TOSHIBA]  31.52 61.44 90 bottom
D26049  DF2B7ASL  [D_06X03_H030_TOSHIBA]  30.57 61.43 270 bottom
D26050  DF2B7ASL  [D_06X03_H030_TOSHIBA]  12.71 53.38 90 bottom
D26051  DF2B7ASL  [D_06X03_H030_TOSHIBA]  13.59 53.4 270 bottom
D26063  DF2B7ASL  [D_06X03_H030_TOSHIBA]  29.03 13.53 90 bottom
D26064  DF2B7ASL  [D_06X03_H030_TOSHIBA]  27.61 13.54 270 bottom
D26065  DF2B7ASL  [D_06X03_H030_TOSHIBA]  22.29 4.91 90 bottom
D26066  DF2B7ASL  [D_06X03_H030_TOSHIBA]  21.3 4.91 270 bottom
D26067  DF2B7ASL  [D_06X03_H030_TOSHIBA]  20.41 4.89 270 bottom
D26069  DF2B7ASL  [D_06X03_H030_TOSHIBA]  21.47 6.45 270 bottom
D26070  DF2B7ASL  [D_06X03_H030_TOSHIBA]  20.53 6.46 270 bottom
D26071  DF2B7ASL  [D_06X03_H030_TOSHIBA]  19.64 6.46 270 bottom
D26072  DF2B7ASL  [D_06X03_H030_TOSHIBA]  18.62 6.26 0 bottom
D26073  DF2B7ASL  [D_06X03_H030_TOSHIBA]  17.71 6.28 0 bottom
D26074  DF2B7ASL  [D_06X03_H030_TOSHIBA]  15.86 6.44 270 bottom
D26075  DF2B7ASL  [D_06X03_H030_TOSHIBA]  14.61 6.44 270 bottom
D26076  DF2B7ASL  [D_06X03_H030_TOSHIBA]  13.29 6.44 270 bottom
D26087  DF2B7ASL  [D_06X03_H030_TOSHIBA]  26.04 13.74 90 bottom
D26088  DF2B7ASL  [D_06X03_H030_TOSHIBA]  24.82 13.74 270 bottom
D26089  DF2B7ASL  [D_06X03_H030_TOSHIBA]  23.44 13.72 90 bottom
D26090  DF2B7ASL  [D_06X03_H030_TOSHIBA]  22.53 13.72 270 bottom
D26091  DF2B7ASL  [D_06X03_H030_TOSHIBA]  17.01 13.81 180 bottom
D26092  DF2B7ASL  [D_06X03_H030_TOSHIBA]  15.7 13.82 180 bottom
D26093  DF2B7ASL  [D_06X03_H030_TOSHIBA]  14.42 13.82 180 bottom
D26094  DF2B7ASL  [D_06X03_H030_TOSHIBA]  13.15 13.82 180 bottom
D26097  DF2B7ASL  [D_06X03_H030_TOSHIBA]  10.75 13.78 180 bottom
D26099  DF2B7ASL  [D_06X03_H030_TOSHIBA]  20.93 13.71 90 bottom
D26100  DF2B7ASL  [D_06X03_H030_TOSHIBA]  7.18 6.71 0 bottom
D26101  DF2B7ASL  [D_06X03_H030_TOSHIBA]  8.36 13.54 90 bottom
D26102  TVW060305VB1SCA1  [D_06X03_H04_INPAQ]  44.25 62.97 180 top
D26103  TVW060305VB1SCA1  [D_06X03_H04_INPAQ]  43.45 62.99 180 top
D26104  TVW060305VB1SCA1  [D_06X03_H04_INPAQ]  43.16 59.13 90 top
D26105  TVW060305VB1SCA1  [D_06X03_H04_INPAQ]  42.26 59.13 270 top
D26201  PJGBLC24C  [SOD323FL_H090_UM]  5.89 45.86 90 bottom
D27001  BLU_LED  [LED0603_H050]  19.47 36.32 225 top
D27002  BLU_LED  [LED0603_H050]  19.47 34.22 225 top
D27003  BLU_LED  [LED0603_H050]  19.47 32.12 225 top
D27004  BLU_LED  [LED0603_H050]  19.47 30.02 225 top
D27005  BLU_LED  [LED0603_H050]  19.47 27.92 225 top
D27006  BLU_LED  [LED0603_H050]  19.47 25.82 225 top
D27007  BLU_LED  [LED0603_H050]  19.47 23.72 225 top
D27008  BLU_LED  [LED0603_H050]  19.47 21.62 225 top
D27009  BLU_LED  [LED0603_H050]  19.47 19.52 225 top
D27010  BLU_LED  [LED0603_H050]  19.47 17.42 225 top
D27011  BLU_LED  [LED0603_H050]  19.47 15.32 225 top
D27012  BLU_LED  [LED0603_H050]  19.47 13.22 225 top
D27013  BLU_LED  [LED0603_H050]  19.47 11.12 225 top
D27014  BLU_LED  [LED0603_H050]  17.47 36.32 225 top
D27015  BLU_LED  [LED0603_H050]  17.47 34.22 225 top
D27016  BLU_LED  [LED0603_H050]  17.47 32.12 225 top
D27017  BLU_LED  [LED0603_H050]  17.47 30.02 225 top
D27018  BLU_LED  [LED0603_H050]  17.47 27.92 225 top
D27019  BLU_LED  [LED0603_H050]  17.47 25.82 225 top
D27020  BLU_LED  [LED0603_H050]  17.47 23.72 225 top
D27021  BLU_LED  [LED0603_H050]  17.47 21.62 225 top
D27022  BLU_LED  [LED0603_H050]  17.47 19.52 225 top
D27023  BLU_LED  [LED0603_H050]  17.47 17.42 225 top
D27024  BLU_LED  [LED0603_H050]  17.47 15.32 225 top
D27025  BLU_LED  [LED0603_H050]  17.47 13.22 225 top
D27026  BLU_LED  [LED0603_H050]  17.47 11.12 225 top
D27027  BLU_LED  [LED0603_H050]  15.47 36.32 225 top
D27028  BLU_LED  [LED0603_H050]  15.47 34.22 225 top
D27029  BLU_LED  [LED0603_H050]  15.47 32.12 225 top
D27030  BLU_LED  [LED0603_H050]  15.47 30.02 225 top
D27031  BLU_LED  [LED0603_H050]  15.47 27.92 225 top
D27032  BLU_LED  [LED0603_H050]  15.47 25.82 225 top
D27033  BLU_LED  [LED0603_H050]  15.47 23.72 225 top
D27034  BLU_LED  [LED0603_H050]  15.47 21.62 225 top
D27035  BLU_LED  [LED0603_H050]  15.47 19.52 225 top
D27036  BLU_LED  [LED0603_H050]  15.47 17.42 225 top
D27037  BLU_LED  [LED0603_H050]  15.47 15.32 225 top
D27038  BLU_LED  [LED0603_H050]  15.47 13.22 225 top
D27039  BLU_LED  [LED0603_H050]  15.47 11.12 225 top
D27040  BLU_LED  [LED0603_H050]  13.47 36.32 225 top
D27041  BLU_LED  [LED0603_H050]  13.47 34.22 225 top
D27042  BLU_LED  [LED0603_H050]  13.47 32.12 225 top
D27043  BLU_LED  [LED0603_H050]  13.47 30.02 225 top
D27044  BLU_LED  [LED0603_H050]  13.47 27.92 225 top
D27045  BLU_LED  [LED0603_H050]  13.47 25.82 225 top
D27046  BLU_LED  [LED0603_H050]  13.47 23.72 225 top
D27047  BLU_LED  [LED0603_H050]  13.47 21.62 225 top
D27048  BLU_LED  [LED0603_H050]  13.47 19.52 225 top
D27049  BLU_LED  [LED0603_H050]  13.47 17.42 225 top
D27050  BLU_LED  [LED0603_H050]  13.47 15.32 225 top
D27051  BLU_LED  [LED0603_H050]  13.47 13.22 225 top
D27052  BLU_LED  [LED0603_H050]  13.47 11.12 225 top
D27053  BLU_LED  [LED0603_H050]  11.47 36.32 225 top
D27054  BLU_LED  [LED0603_H050]  11.47 34.22 225 top
D27055  BLU_LED  [LED0603_H050]  11.47 32.12 225 top
D27056  BLU_LED  [LED0603_H050]  11.47 30.02 225 top
D27057  BLU_LED  [LED0603_H050]  11.47 27.92 225 top
D27058  BLU_LED  [LED0603_H050]  11.47 25.82 225 top
D27059  BLU_LED  [LED0603_H050]  11.47 23.72 225 top
D27060  BLU_LED  [LED0603_H050]  11.47 21.62 225 top
D27061  BLU_LED  [LED0603_H050]  11.47 19.52 225 top
D27062  BLU_LED  [LED0603_H050]  11.47 17.42 225 top
D27063  BLU_LED  [LED0603_H050]  11.47 15.32 225 top
D27064  BLU_LED  [LED0603_H050]  11.47 13.22 225 top
D27065  BLU_LED  [LED0603_H050]  11.47 11.12 225 top
D27066  BLU_LED  [LED0603_H050]  9.47 36.32 225 top
D27067  BLU_LED  [LED0603_H050]  9.47 34.22 225 top
D27068  BLU_LED  [LED0603_H050]  9.47 32.12 225 top
D27069  BLU_LED  [LED0603_H050]  9.47 30.02 225 top
D27070  BLU_LED  [LED0603_H050]  9.47 27.92 225 top
D27071  BLU_LED  [LED0603_H050]  9.47 25.82 225 top
D27072  BLU_LED  [LED0603_H050]  9.47 23.72 225 top
D27073  BLU_LED  [LED0603_H050]  9.47 21.62 225 top
D27074  BLU_LED  [LED0603_H050]  9.47 19.52 225 top
D27075  BLU_LED  [LED0603_H050]  9.47 17.42 225 top
D27076  BLU_LED  [LED0603_H050]  9.47 15.32 225 top
D27077  BLU_LED  [LED0603_H050]  9.47 13.22 225 top
D27078  BLU_LED  [LED0603_H050]  9.47 11.12 225 top
D27079  BLU_LED  [LED0603_H050]  7.47 36.32 225 top
D27080  BLU_LED  [LED0603_H050]  7.47 34.22 225 top
D27081  BLU_LED  [LED0603_H050]  7.47 32.12 225 top
D27082  BLU_LED  [LED0603_H050]  7.47 30.02 225 top
D27083  BLU_LED  [LED0603_H050]  7.47 27.92 225 top
D27084  BLU_LED  [LED0603_H050]  7.47 25.82 225 top
D27085  BLU_LED  [LED0603_H050]  7.47 23.72 225 top
D27086  BLU_LED  [LED0603_H050]  7.47 21.62 225 top
D27087  BLU_LED  [LED0603_H050]  7.47 19.52 225 top
D27088  BLU_LED  [LED0603_H050]  7.47 17.42 225 top
D27089  BLU_LED  [LED0603_H050]  7.47 15.32 225 top
D27090  BLU_LED  [LED0603_H050]  7.47 13.22 225 top
D27091  BLU_LED  [LED0603_H050]  7.37 11.34 225 top
D27092  BLU_LED  [LED0603_H050]  5.47 36.32 225 top
D27093  BLU_LED  [LED0603_H050]  5.47 34.22 225 top
D27094  BLU_LED  [LED0603_H050]  5.47 32.12 225 top
D27095  BLU_LED  [LED0603_H050]  5.47 30.02 225 top
D27096  BLU_LED  [LED0603_H050]  5.47 27.92 225 top
D27097  BLU_LED  [LED0603_H050]  5.47 25.82 225 top
D27098  BLU_LED  [LED0603_H050]  5.47 23.72 225 top
D27099  BLU_LED  [LED0603_H050]  5.47 21.62 225 top
D27100  BLU_LED  [LED0603_H050]  5.47 19.52 225 top
D27101  BLU_LED  [LED0603_H050]  5.47 17.42 225 top
D27102  BLU_LED  [LED0603_H050]  5.47 15.32 225 top
D27103  BLU_LED  [LED0603_H050]  5.47 13.22 225 top
D27104  BLU_LED  [LED0603_H050]  5.47 11.12 225 top
D27201  GRN_LED  [LED0603_H090]  31.85 66.41 180 top
D27301  RED_BLU_GRN_LED4P  [LED4_10X10_A1_H04]  44.07 3.56 270 top
D27302  RED_BLU_GRN_LED4P  [LED4_10X10_A1_H04]  42.16 3.56 270 top
D27401  RED_BLU_GRN_LED4P  [LED4_10X10_A1_H04]  45.97 3.56 270 top
D27402  RED_BLU_GRN_LED4P  [LED4_10X10_A1_H04]  47.88 3.56 270 top
DRAM1  MT53E512M32D1ZW-046_WT_B  [BGA200P_145X100_H110]  41.86 34.28 180 top
EMMC1  EMMC16G-MW28-GA01_BGA153P  [BGA153P_130X115_05_H090]  25.97 21.55 90 bottom
F501  BEAD_120  [BEAD0402_H060]  43.96 18.76 0 top
JANALOG1  20TW-995  [HEAD14_387X25_2D54_H87_F]  2.54 40.64 270 top
JBTN1  TS-A57AHNP-2-W-S085  [SW5_85X64_H34_P12]  49.4 62.74 270 top
JCTL1  P302V-2X5-ST2-RT  [HEAD2X5P_127X62_254_H970_M]  44.45 50.08 0 top
JDIGITAL1  20TW-994  [HEAD18_477X25_2D54_H87_F]  50.8 5.08 90 top
JMEDIA1  SM2554V6-2X30-SMT-G5-1-RT  [HEAD2X30_385X50_1D27_H48_F_R_P]  26.67 56.9 270 bottom
JMISC1  SM2554V6-2X30-SMT-G5-1-RT  [HEAD2X30_385X50_1D27_H48_F_R_P]  26.67 10.03 270 bottom
JSPI1  HD2X03C-R3H-HH  [HEAD2X3_76X50_2D54_H87_M_PIP]  30.49 4.91 180 top
JUSB1  USB3-24CSW-R9H-H  [USB2X12_89X81_H35]  37.85 65.06 270 top
L601  1UH/4.2A  [L_25X20_H10_D]  44.1 11.96 90 top
L1001  470NH/4.7A  [CHOKE_200X160_H100_A]  39.88 21.29 180 top
L1002  470NH/4.7A  [CHOKE_200X160_H100_A]  36.58 21.26 180 top
L1003  470NH/4.7A  [CHOKE_200X160_H100_A]  32.38 20.83 270 top
L1004  470NH/4.7A  [CHOKE_200X160_H100_A]  31.67 17.53 270 top
L2801  1UH/4.2A  [L_25X20_H10_D]  10.56 45.18 90 bottom
L2802  1UH/4.2A  [L_25X20_H10_D]  9.5 37.39 90 bottom
L2803  3.3UH/4.3A  [CHOKE_60X59_H45_INPAQ]  14.16 41.93 90 top
MCU1  STM32U585AII6TR_BGA169P  [BGA169_70_0D5_H06]  11.9 24.61 270 bottom
NOREF  -  []  30.53 32.41 90 top
NOREF#2  -  []  45.55 33.1 90 top
NOREF#3  -  []  20.86 15.24 0 top
NOREF#4  -  []  12.96 18.98 90 top
NOREF#5  -  []  28.8 55.33 0 top
NOREF#6  -  []  29.14 32.41 0 top
NOREF#7  -  []  12.79 53.02 0 top
NOREF#8  -  []  46.23 46.71 0 top
NOREF#9  -  []  37.94 42.74 90 top
NOREF#10  -  []  15.57 13.63 90 top
NOREF#11  -  []  18.01 50.09 90 top
NOREF#12  -  []  5.43 57.11 0 top
NOREF#13  -  []  34.8 11.89 0 top
NOREF#14  -  []  29.83 61.45 90 top
NOREF#15  -  []  30.62 21.07 0 top
NOREF#16  -  []  32.38 36.21 90 top
NOREF#17  -  []  43.36 48.14 0 top
NOREF#18  -  []  15.3 20.4 0 top
NOREF#19  -  []  36.7 52.56 90 top
NOREF#20  -  []  35.77 40.48 90 top
NOREF#21  -  []  46.07 18.62 90 top
NOREF#22  -  []  7.6 50.87 0 top
NOREF#23  -  []  37.38 20.26 0 top
NOREF#24  -  []  32.57 49.59 90 top
NOREF#25  -  [unnamed#2]  2.52 58.98 0 top
NOREF#26  -  []  38.81 53.23 0 top
NOREF#27  -  []  44.17 4.91 0 top
NOREF#28  -  []  37.64 43.34 0 top
NOREF#29  -  []  7.86 65.13 0 top
NOREF#30  -  []  18.58 36.25 90 top
NOREF#31  -  []  17.85 31.29 90 top
NOREF#32  -  []  41.71 4.01 0 top
NOREF#33  -  []  26.2 31.64 90 top
NOREF#34  -  []  13.86 49.13 90 top
NOREF#35  -  []  26.36 34.96 90 top
NOREF#36  -  []  10.95 0.32 0 top
NOREF#37  -  []  27.48 13.35 90 top
NOREF#38  -  []  32.79 29.83 90 top
NOREF#39  -  []  43.23 16.92 90 top
NOREF#40  -  []  48 57.02 0 top
NOREF#41  -  []  13.09 30.7 90 top
NOREF#42  -  []  43.23 15.87 90 top
NOREF#43  -  []  14.49 6.25 90 top
NOREF#44  -  []  28.68 35.21 0 top
NOREF#45  -  []  33.95 24.8 0 top
NOREF#46  -  []  40.25 26.68 90 top
NOREF#47  -  []  16.65 38.62 0 top
NOREF#48  -  []  28.46 30.71 90 top
NOREF#49  -  []  42.89 59.48 0 top
NOREF#50  -  []  36.55 10.44 90 top
NOREF#51  -  []  34.45 14.28 90 top
NOREF#52  -  []  34.03 23.1 0 top
NOREF#53  -  []  22.88 14.23 90 top
NOREF#54  -  []  13.64 19.61 90 top
NOREF#55  -  []  38.53 5.78 0 top
NOREF#56  -  []  29.28 35.21 90 top
NOREF#57  -  []  23.58 62.85 0 top
NOREF#58  -  []  32.39 14.3 90 top
NOREF#59  -  []  12.4 53.22 0 top
NOREF#60  -  []  25.74 34.03 0 top
NOREF#61  -  []  33.12 50.37 90 top
NOREF#62  -  []  26.36 33.57 0 top
NOREF#63  -  []  9.5 36.14 90 top
NOREF#64  -  []  42.63 17.43 0 top
NOREF#65  -  []  36.19 52.56 90 top
NOREF#66  -  []  42.84 58.24 0 top
NOREF#67  -  []  16.85 14.12 0 top
NOREF#68  -  []  28.45 57.12 0 top
NOREF#69  -  []  29.6 21.07 0 top
NOREF#70  -  []  26.86 31.21 90 top
NOREF#71  -  []  37.56 53.12 0 top
NOREF#72  -  []  30.67 18.33 90 top
NOREF#73  -  []  32.06 31.42 0 top
NOREF#74  -  []  31.73 16.1 0 top
NOREF#75  -  []  15.05 43.9 0 top
NOREF#76  -  []  10.01 18.79 0 top
NOREF#77  -  []  44.13 62.88 0 top
NOREF#78  -  []  31.59 33.02 0 top
NOREF#79  -  []  38.12 27.51 0 top
NOREF#80  -  []  11.54 33.15 90 top
NOREF#81  -  []  10.91 13.47 90 top
NOREF#82  -  []  26.11 13.85 0 top
NOREF#83  -  []  42.95 32.67 0 top
NOREF#84  -  []  21.55 3.31 90 top
NOREF#85  -  []  28.31 35.12 0 top
NOREF#86  -  []  22.89 53.75 0 top
NOREF#87  -  []  29.14 38.23 90 top
NOREF#88  -  []  39.25 43.46 0 top
NOREF#89  -  []  7.86 57.13 0 top
NOREF#90  -  []  38.72 52.52 90 top
NOREF#91  -  []  29.14 33.01 90 top
NOREF#92  -  []  17.73 64.55 0 top
NOREF#93  -  []  37.3 11.04 0 top
NOREF#94  -  []  14.3 13.63 90 top
NOREF#95  -  []  10.44 20.37 0 top
NOREF#96  -  []  41.26 22.12 0 top
NOREF#97  -  []  42.17 61.86 90 top
NOREF#98  -  []  45.32 15.6 0 top
NOREF#99  -  []  35.52 41.43 90 top
NOREF#100  -  []  38.18 29.56 90 top
NOREF#101  -  []  51.05 59.19 0 top
NOREF#102  -  []  28.63 38.24 90 top
NOREF#103  -  []  31.99 26.12 90 top
NOREF#104  -  []  19.05 49.79 0 top
NOREF#105  -  []  17.14 45.18 90 top
NOREF#106  -  []  8.9 21.61 90 top
NOREF#107  -  []  41.25 63.21 0 top
NOREF#108  -  []  34.4 13.84 0 top
NOREF#109  -  []  43.5 24.23 0 top
NOREF#110  -  []  37.97 50.54 0 top
NOREF#111  -  []  31.75 50.31 0 top
NOREF#112  -  []  31.53 38.71 90 top
NOREF#113  -  []  37.84 17.12 90 top
NOREF#114  -  []  46.17 13.41 0 top
NOREF#115  -  []  12.98 6.31 0 top
NOREF#116  -  []  35.4 11.89 90 top
NOREF#117  -  []  20.28 4.69 90 top
NOREF#118  -  []  43.57 62.81 90 top
NOREF#119  -  []  13.31 13.51 90 top
NOREF#120  -  []  2.54 15.24 90 top
NOREF#121  -  []  15.74 47.59 90 top
NOREF#122  -  []  49 58.49 90 top
NOREF#123  -  []  12.98 6.6 0 top
NOREF#124  -  []  7.26 28.45 90 top
NOREF#125  -  []  14.13 31.45 0 top
NOREF#126  -  []  26.77 37.21 90 top
NOREF#127  -  []  31.83 10.85 90 top
NOREF#128  -  []  5.44 49.74 0 top
NOREF#129  -  []  4.79 59.92 0 top
NOREF#130  -  []  33.42 30.25 0 top
NOREF#131  -  []  14.99 37.82 90 top
NOREF#132  -  []  46.86 27.03 90 top
NOREF#133  -  []  38.71 43.35 0 top
NOREF#134  -  []  25 16.2 0 top
NOREF#135  -  []  43.21 21.14 90 top
NOREF#136  -  []  36.7 53.46 0 top
NOREF#137  -  []  37.81 12.13 0 top
NOREF#138  -  []  33.06 32.42 0 top
NOREF#139  -  []  31.07 32.41 90 top
NOREF#140  -  []  32.79 30.34 90 top
NOREF#141  -  []  15.34 50.09 0 top
NOREF#142  -  []  44.84 57.52 90 top
NOREF#143  -  []  30.53 33.01 0 top
NOREF#144  -  []  22.48 4.07 90 top
NOREF#145  -  []  15.45 49.58 90 top
NOREF#146  -  []  32.99 15.82 0 top
NOREF#147  -  []  38.16 43.34 0 top
NOREF#148  -  []  46.92 4.06 90 top
NOREF#149  -  []  10.23 28.73 0 top
NOREF#150  -  []  40.31 8.78 90 top
NOREF#151  -  []  7.62 20.01 90 top
NOREF#152  -  []  27.01 29.28 0 top
NOREF#153  -  []  16.46 23.45 90 top
NOREF#154  -  []  17.56 45.53 90 top
NOREF#155  -  []  23.04 60.09 0 top
NOREF#156  -  []  30.81 29.87 90 top
NOREF#157  -  []  4.5 60.95 0 top
NOREF#158  -  []  33.31 34.78 0 top
NOREF#159  -  []  28.36 16.6 0 top
NOREF#160  -  []  43.46 43.05 0 top
NOREF#161  -  []  27.29 13.41 90 top
NOREF#162  -  []  26.53 35.59 90 top
NOREF#163  -  []  46.12 21.66 90 top
NOREF#164  -  []  42.43 43.09 0 top
NOREF#165  -  []  6.51 48.88 90 top
NOREF#166  -  []  35.86 49.13 90 top
NOREF#167  -  []  31.73 30.25 0 top
NOREF#168  -  []  34.18 19.76 90 top
NOREF#169  -  []  42.26 21.1 90 top
NOREF#170  -  []  35.48 10.26 0 top
NOREF#171  -  []  11.85 14.12 90 top
NOREF#172  -  []  31.09 37.5 90 top
NOREF#173  -  []  19.33 6.62 0 top
NOREF#174  -  []  27.81 33.68 0 top
NOREF#175  -  []  42.35 32 0 top
NOREF#176  -  []  46.18 11.75 0 top
NOREF#177  -  []  31 31.27 90 top
NOREF#178  -  []  34.2 21.48 90 top
NOREF#179  -  []  33.12 50.91 90 top
NOREF#180  -  []  29.68 38.23 90 top
NOREF#181  -  []  16.29 31.24 90 top
NOREF#182  -  []  4.53 63.04 90 top
NOREF#183  -  []  46.23 47.26 0 top
NOREF#184  -  []  35.06 50.63 0 top
NOREF#185  -  []  31.48 26.12 90 top
NOREF#186  -  []  40.55 39.8 90 top
NOREF#187  -  []  32.65 19.68 0 top
NOREF#188  -  []  41.45 32 0 top
NOREF#189  -  []  14.96 32.05 90 top
NOREF#190  -  []  38.81 51.99 0 top
NOREF#191  -  []  45.12 22.67 0 top
NOREF#192  -  []  42.63 16.92 0 top
NOREF#193  -  []  21.97 39.16 90 top
NOREF#194  -  []  15 29.64 0 top
NOREF#195  -  []  26.23 37.21 90 top
NOREF#196  -  []  35.75 26.25 90 top
NOREF#197  -  []  12.98 6.28 90 top
NOREF#198  -  []  22.25 29.25 90 top
NOREF#199  -  []  21.67 40.32 0 top
NOREF#200  -  []  42.05 32.98 0 top
NOREF#201  -  []  17.55 5.97 0 top
NOREF#202  -  []  4.79 57.84 90 top
NOREF#203  -  []  23.32 13.52 90 top
NOREF#204  -  []  14.22 19.61 90 top
NOREF#205  -  []  13.46 53.21 90 top
NOREF#206  -  []  12.47 20.6 90 top
NOREF#207  -  []  23.88 62.25 90 top
NOREF#208  -  []  44.21 18.26 90 top
NOREF#209  -  []  42.63 16.39 0 top
NOREF#210  -  []  36.45 17.54 90 top
NOREF#211  -  []  35.88 55.64 0 top
NOREF#212  -  []  28.8 55.33 0 top
NOREF#213  -  []  25.14 34.03 90 top
NOREF#214  -  []  12.77 36.04 0 top
NOREF#215  -  []  35.13 22.5 0 top
NOREF#216  -  []  39.4 11.09 0 top
NOREF#217  -  []  34.18 20.39 90 top
NOREF#218  -  []  39.36 5.26 90 top
NOREF#219  -  []  18.26 6.19 0 top
NOREF#220  -  []  27.86 30.71 0 top
NOREF#221  -  []  22.58 14.83 0 top
NOREF#222  -  []  38.87 12.13 0 top
NOREF#223  -  []  4.53 62.3 90 top
NOREF#224  -  []  18.5 6.07 90 top
NOREF#225  -  []  22.69 40.32 0 top
NOREF#226  -  []  31.7 57.7 90 top
NOREF#227  -  []  11.87 20.6 0 top
NOREF#228  -  []  27.86 29.22 0 top
NOREF#229  -  []  39.1 34.95 90 top
NOREF#230  -  []  37.84 16.12 90 top
NOREF#231  -  []  38.29 18.26 90 top
NOREF#232  -  []  16.74 20.71 90 top
NOREF#233  -  []  30.32 35.23 90 top
NOREF#234  -  []  36.07 49.73 0 top
NOREF#235  -  []  27.21 32.83 90 top
NOREF#236  -  []  7.1 4.77 0 top
NOREF#237  -  []  36.39 57.45 0 top
NOREF#238  -  []  36 51.85 90 top
NOREF#239  -  []  40.25 35.1 90 top
NOREF#240  -  []  20.99 4.79 0 top
NOREF#241  -  []  15.73 6.25 90 top
NOREF#242  -  []  8.4 28.11 0 top
NOREF#243  -  []  26.18 34.44 90 top
NOREF#244  -  []  14.3 14.13 0 top
NOREF#245  -  []  11.61 15.59 90 top
NOREF#246  -  []  7.6 45.57 90 top
NOREF#247  -  []  42.66 3.06 90 top
NOREF#248  -  []  30.24 34.16 90 top
NOREF#249  -  []  36.37 49.13 90 top
NOREF#250  -  []  7.87 21.37 90 top
NOREF#251  -  []  28.45 36.24 0 top
NOREF#252  -  []  35.7 52.45 0 top
NOREF#253  -  []  39.11 54.31 90 top
NOREF#254  -  []  27.08 36.19 0 top
NOREF#255  -  []  26.82 30.67 90 top
NOREF#256  -  []  22.72 24.8 90 top
NOREF#257  -  []  21.53 2.68 90 top
NOREF#258  -  []  37.41 58.06 0 top
NOREF#259  -  []  29.04 34.07 0 top
NOREF#260  -  []  7.02 6.4 0 top
NOREF#261  -  []  46.34 43.41 90 top
NOREF#262  -  []  33.69 12.8 90 top
NOREF#263  -  []  15.4 39.02 0 top
NOREF#264  -  []  29.32 13.2 0 top
NOREF#265  -  []  29.85 18.44 90 top
NOREF#266  -  []  47.17 13.41 90 top
NOREF#267  -  []  37.38 55.68 0 top
NOREF#268  -  []  41.26 21.1 0 top
NOREF#269  -  []  18.46 5.95 0 top
NOREF#270  -  []  25.85 57.03 90 top
NOREF#271  -  []  38.86 6.26 0 top
NOREF#272  -  []  38.22 21.23 90 top
NOREF#273  -  []  25.31 35.59 90 top
NOREF#274  -  []  14.45 59.96 0 top
NOREF#275  -  []  38.84 51.21 0 top
NOREF#276  -  []  32.06 36.55 0 top
NOREF#277  -  []  29.46 64.99 90 top
NOREF#278  -  []  30.6 35.75 0 top
NOREF#279  -  []  21.12 4.67 0 top
NOREF#280  -  []  44.96 18.98 0 top
NOREF#281  -  []  38.95 30.98 0 top
NOREF#282  -  []  27.63 60.98 0 top
NOREF#283  -  []  20.34 4.01 90 top
NOREF#284  -  []  44.1 61.16 0 top
NOREF#285  -  []  28.63 37.64 0 top
NOREF#286  -  []  27.42 30.67 0 top
NOREF#287  -  []  11.52 43.17 0 top
NOREF#288  -  []  29.6 22.07 90 top
NOREF#289  -  []  43.6 60.56 90 top
NOREF#290  -  []  31.6 31.27 0 top
NOREF#291  -  []  22.99 38.11 90 top
NOREF#292  -  []  37.38 56.28 90 top
NOREF#293  -  []  30.81 30.47 0 top
NOREF#294  -  []  37.58 29.56 0 top
NOREF#295  -  []  37.23 30.91 0 top
NOREF#296  -  []  26.2 32.29 90 top
NOREF#297  -  []  47.98 4.91 0 top
NOREF#298  -  []  25.91 35.59 0 top
NOREF#299  -  []  22.99 38.65 90 top
NOREF#300  -  []  12.85 5.1 0 top
NOREF#301  -  []  10.25 60.8 0 top
NOREF#302  -  []  14.96 31.45 0 top
NOREF#303  -  []  30.38 31.4 0 top
NOREF#304  -  []  21.28 4.52 0 top
NOREF#305  -  []  45.12 21.66 0 top
NOREF#306  -  []  7.5 27.31 0 top
NOREF#307  -  []  7.02 6.4 90 top
NOREF#308  -  []  12.09 39.74 90 top
NOREF#309  -  []  47.01 56.99 90 top
NOREF#310  -  []  39.25 31.3 90 top
NOREF#311  -  []  29.05 35.73 90 top
NOREF#312  -  []  15.95 25.93 90 top
NOREF#313  -  []  16.53 24.36 90 top
NOREF#314  -  []  37.17 38.26 90 top
NOREF#315  -  []  25.17 76.15 0 top
NOREF#316  -  []  16.23 24.96 0 top
NOREF#317  -  []  28.86 29.22 90 top
NOREF#318  -  []  40.47 37.51 90 top
NOREF#319  -  []  10.56 43.93 90 top
NOREF#320  -  []  48.83 3.61 90 top
NOREF#321  -  []  39.63 42.92 90 top
NOREF#322  -  []  45.89 17.21 0 top
NOREF#323  -  []  20.1 5.05 0 top
NOREF#324  -  []  44.21 23.17 0 top
NOREF#325  -  []  39.5 55.87 90 top
NOREF#326  -  []  6.47 25.38 0 top
NOREF#327  -  []  31.92 15.17 0 top
NOREF#328  -  []  44.2 43.09 0 top
NOREF#329  -  []  45.29 17.84 90 top
NOREF#330  -  []  37.29 42.87 90 top
NOREF#331  -  []  38.16 52.52 90 top
NOREF#332  -  []  31.79 13.45 0 top
NOREF#333  -  []  30.49 7.45 0 top
NOREF#334  -  []  42.56 58.98 0 top
NOREF#335  -  []  37.54 6.75 0 top
NOREF#336  -  []  25.69 31.04 0 top
NOREF#337  -  []  6.37 26.88 0 top
NOREF#338  -  []  15.01 6.53 90 top
NOREF#339  -  []  44.4 60.56 90 top
NOREF#340  -  []  28.91 63.91 0 top
NOREF#341  -  []  32 58.81 0 top
NOREF#342  -  []  31.73 15.5 90 top
NOREF#343  -  []  30.49 7.45 0 top
NOREF#344  -  []  39.45 4.93 0 top
NOREF#345  -  []  44.22 15.71 90 top
NOREF#346  -  []  21.97 36.97 90 top
NOREF#347  -  []  42.26 22.12 90 top
NOREF#348  -  []  20.1 4.76 0 top
NOREF#349  -  []  28.23 32.6 0 top
NOREF#350  -  []  14.2 39.12 0 top
NOREF#351  -  []  11.45 31.48 0 top
NOREF#352  -  []  19.33 6.34 0 top
NOREF#353  -  []  6.75 36.49 0 top
NOREF#354  -  []  3.93 60.64 90 top
NOREF#355  -  []  46.45 44.87 90 top
NOREF#356  -  []  47.24 56.79 90 top
NOREF#357  -  []  23.42 14.23 90 top
NOREF#358  -  []  44.66 57.84 0 top
NOREF#359  -  []  10.94 35.55 0 top
NOREF#360  -  []  25.68 14.93 0 top
NOREF#361  -  []  42.2 4.84 90 top
NOREF#362  -  []  25.55 61.39 0 top
NOREF#363  -  []  10.9 31.85 90 top
NOREF#364  -  []  27.85 30.1 0 top
NOREF#365  -  []  17.63 25.22 0 top
NOREF#366  -  []  39.4 12.15 0 top
NOREF#367  -  []  37.38 22.26 90 top
NOREF#368  -  []  27.94 31.51 0 top
NOREF#369  -  []  25.76 32.34 0 top
NOREF#370  -  []  14.07 46.88 0 top
NOREF#371  -  []  49.55 48.8 90 top
NOREF#372  -  []  30.29 29.75 90 top
NOREF#373  -  []  39.39 14.53 0 top
NOREF#374  -  []  31.69 26.72 0 top
NOREF#375  -  []  17.55 5.97 90 top
NOREF#376  -  []  6.67 26.28 90 top
NOREF#377  -  []  34.01 10.21 0 top
NOREF#378  -  []  11.98 50.09 0 top
NOREF#379  -  []  36.76 49.73 0 top
NOREF#380  -  []  50.8 26.92 90 top
NOREF#381  -  []  41.81 10.46 90 top
NOREF#382  -  []  35.14 15.42 0 top
NOREF#383  -  []  44.82 42.77 90 top
NOREF#384  -  []  30.2 13.26 90 top
NOREF#385  -  []  37.3 10.44 90 top
NOREF#386  -  []  12.98 39.45 90 top
NOREF#387  -  []  25.3 15.6 90 top
NOREF#388  -  []  25.74 33.68 90 top
NOREF#389  -  []  34.95 49.56 90 top
NOREF#390  -  []  46.26 27.46 90 top
NOREF#391  -  []  44.6 33.25 0 top
NOREF#392  -  []  13.71 6.73 0 top
NOREF#393  -  []  32 58.3 0 top
NOREF#394  -  []  19.12 31.76 90 top
NOREF#395  -  []  28.8 52.13 90 top
NOREF#396  -  []  42.56 59.28 90 top
NOREF#397  -  []  32.66 31.42 90 top
NOREF#398  -  []  32.63 31.65 0 top
NOREF#399  -  []  37.29 49.73 0 top
NOREF#400  -  []  30.64 26.72 0 top
NOREF#401  -  []  31.78 34.11 0 top
NOREF#402  -  []  33.17 37.16 0 top
NOREF#403  -  []  28.45 30.1 90 top
NOREF#404  -  []  28.96 65.99 0 top
NOREF#405  -  []  41.65 33.9 90 top
NOREF#406  -  []  21.16 6.29 90 top
NOREF#407  -  []  33.66 32.96 90 top
NOREF#408  -  []  16.89 14.12 0 top
NOREF#409  -  []  26.77 36.61 0 top
NOREF#410  -  []  32.19 30.85 0 top
NOREF#411  -  []  15.3 28.44 90 top
NOREF#412  -  []  14.58 13.51 90 top
NOREF#413  -  []  31.45 65.61 0 top
NOREF#414  -  []  44.73 30.54 0 top
NOREF#415  -  []  21.24 13.55 90 top
NOREF#416  -  []  32.8 18.91 0 top
NOREF#417  -  []  40.55 31.4 0 top
NOREF#418  -  []  27.76 33.89 90 top
NOREF#419  -  []  37.92 56.28 90 top
NOREF#420  -  []  43.62 4.01 0 top
NOREF#421  -  []  13.28 53.24 90 top
